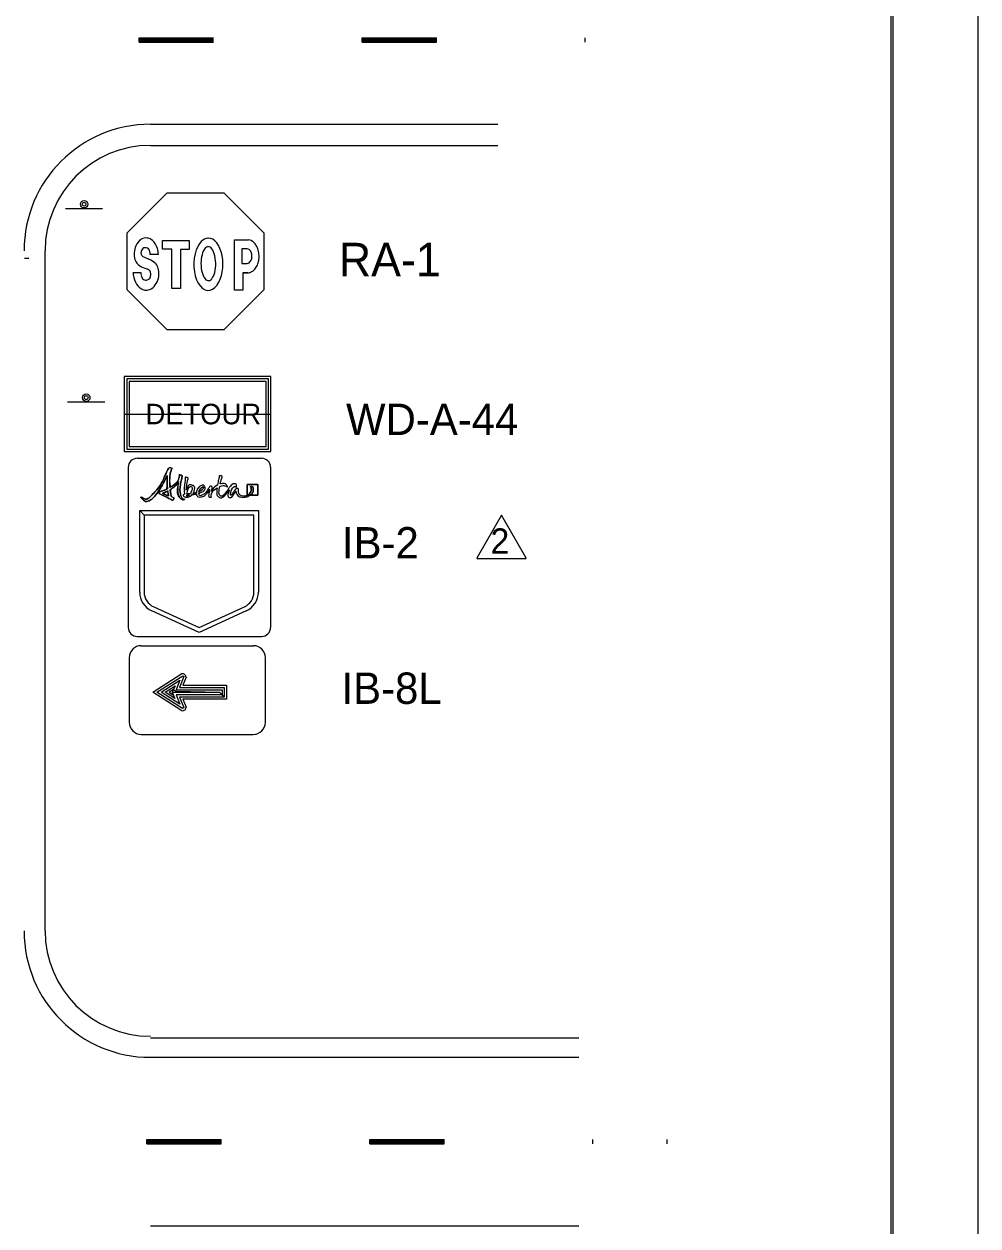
# Model space of a CAD drawing. Extents: x 1482 to 1692, y 225 to 494.
# Drawn here: x 1637.6 to 1692.4, y 314.2 to 383.2 of the extents above; entities that cross this region are included whole.
import ezdxf

# ---------------------------------------------------------------- set-up
doc = ezdxf.new("R2010")
doc.units = 0
for name, color, linetype in [('Level 17', 7, 'Continuous'), ('Level 2', 7, 'Continuous'), ('Level 53', 7, 'Continuous'), ('Level 60', 7, 'Continuous')]:
    doc.layers.add(name, color=color, linetype=linetype)

msp = doc.modelspace()

# ---------------------------------------------------------------- linework, layer by layer
at = {"layer": 'Level 17'}
for p, q in [((1640.01, 372.609), (1642.143, 372.609)), ((1645.583, 370.269), (1645.583, 370.772)), ((1645.583, 370.772), (1647.113, 370.772)), ((1647.113, 370.772), (1647.113, 370.257)), ((1648.171, 370.41), (1648.191, 370.414)), ((1648.191, 370.899), (1648.205, 370.9)), ((1649.717, 367.924), (1649.717, 370.798)), ((1649.717, 370.798), (1650.521, 370.798)), ((1637.65, 369.75), (1637.906, 369.75)), ((1645.349, 369.969), (1644.857, 369.969)), ((1646.111, 370.269), (1645.583, 370.269)), ((1646.111, 368.008), (1646.111, 370.269)), ((1647.113, 370.257), (1646.609, 370.257)), ((1646.609, 370.257), (1646.609, 368.008)), ((1650.137, 370.282), (1650.137, 369.447)), ((1650.449, 370.282), (1650.137, 370.282)), ((1650.449, 370.282), (1650.137, 370.282)), ((1650.137, 370.282), (1650.137, 369.447)), ((1650.137, 369.447), (1650.443, 369.447)), ((1650.137, 369.447), (1650.443, 369.447)), ((1643.893, 368.937), (1644.343, 368.937)), ((1644.035, 368.368), (1644.033, 368.37)), ((1650.481, 368.912), (1650.195, 368.904)), ((1650.195, 368.904), (1650.495, 368.904)), ((1650.195, 368.904), (1650.195, 367.924)), ((1646.609, 368.008), (1646.111, 368.008)), ((1650.195, 367.924), (1649.717, 367.924)), ((1640.136, 361.512), (1642.269, 361.512)), ((1643.382, 360.81), (1651.819, 360.81)), ((1644.367, 347.509), (1650.804, 347.509)), ((1643.683, 343.125), (1643.683, 346.823)), ((1651.482, 346.823), (1651.482, 343.125)), ((1645.021, 344.843), (1646.634, 345.873)), ((1646.935, 345.707), (1646.743, 345.247)), ((1646.743, 345.247), (1649.258, 345.247)), ((1649.258, 345.247), (1649.258, 344.447)), ((1646.634, 343.819), (1645.021, 344.843)), ((1646.743, 344.447), (1646.941, 343.985)), ((1649.258, 344.447), (1646.749, 344.447)), ((1644.17, 342.776), (1644.17, 342.776)), ((1644.361, 342.428), (1650.798, 342.428))]:
    msp.add_line(p, q, dxfattribs=at)
for points in [[(1651.407, 367.944), (1649.113, 365.65), (1645.846, 365.65), (1643.553, 367.944), (1643.553, 371.211), (1645.846, 373.503), (1649.113, 373.503), (1651.407, 371.211)], [(1651.813, 362.964), (1643.388, 362.964), (1643.388, 358.656), (1651.813, 358.656)], [(1651.672, 362.822), (1643.527, 362.822), (1643.527, 358.796), (1651.672, 358.796)], [(1651.532, 362.683), (1643.668, 362.683), (1643.668, 358.938), (1651.532, 358.938)]]:
    msp.add_lwpolyline(points, close=True, dxfattribs=at)
for points in [[(1649.124, 344.569), (1646.551, 344.569), (1646.806, 343.973), (1646.737, 343.909), (1645.258, 344.843), (1646.743, 345.791), (1646.814, 345.752), (1646.551, 345.119), (1649.13, 345.119), (1649.124, 344.569), (1649.002, 344.702), (1646.359, 344.702), (1646.582, 344.151), (1645.501, 344.843), (1646.582, 345.535), (1646.359, 344.984), (1649.002, 344.984), (1649.002, 344.702), (1648.867, 344.831), (1646.148, 344.831), (1646.294, 344.485), (1645.738, 344.843), (1646.308, 345.207), (1646.224, 345.003), (1645.969, 344.843), (1646.212, 344.683), (1646.161, 344.849), (1646.224, 345.003), (1646.353, 344.913), (1648.861, 344.849), (1648.867, 344.831)], [(1649.124, 344.569), (1646.551, 344.569)]]:
    msp.add_lwpolyline(points, dxfattribs=at)
for centre, radius in [((1641.081, 372.847), 0.213), ((1641.081, 372.847), 0.107), ((1641.207, 361.751), 0.213), ((1641.207, 361.751), 0.107)]:
    msp.add_circle(centre, radius, dxfattribs=at)
for centre, radius, start, end in [((1645.178, 370.002), 1.219, 157.73321, 177.13918), ((1644.843, 370.107), 0.87, 123.3662, 155.67344), ((1644.643, 370.381), 0.532, 46.13686, 121.39871), ((1644.421, 370.089), 0.898, 14.56402, 49.00631), ((1650.479, 370.326), 0.477, 44.85284, 85.0441), ((1650.33, 370.116), 0.732, 29.22414, 48.53082), ((1650.33, 370.116), 0.732, 29.22414, 48.53082), ((1650.32, 370.045), 0.778, 13.06738, 33.76202), ((1645.027, 369.968), 1.071, 174.81715, 195.91834), ((1644.587, 370.061), 0.242, 164.13099, 238.14757), ((1644.619, 370.099), 0.264, 113.8064, 172.24074), ((1645.35, 371.28), 1.68, 237.98164, 250.97904), ((1644.598, 370.078), 0.277, 47.30173, 109.01194), ((1644.468, 370.029), 0.405, 350.44122, 39.32441), ((1644.364, 368.602), 1.175, 46.24648, 67.92633), ((1644.103, 369.947), 1.243, 0.69518, 17.14515), ((1650.402, 370.011), 0.283, 35.11978, 79.31166), ((1650.402, 370.011), 0.283, 35.11978, 79.31166), ((1650.269, 369.926), 0.44, 8.60306, 34.21696), ((1650.269, 369.926), 0.44, 8.60306, 34.21696), ((1650.297, 369.813), 0.418, 326.50855, 357.0313), ((1650.297, 369.813), 0.418, 326.50855, 357.0313), ((1650.253, 369.869), 0.468, 350.34165, 15.23421), ((1650.253, 369.869), 0.468, 350.34165, 15.23421), ((1649.622, 369.815), 1.512, 3.39027, 15.65974), ((1649.917, 369.845), 1.215, 349.75207, 2.79164), ((1649.917, 369.845), 1.215, 349.75207, 2.79164), ((1644.712, 369.937), 0.762, 200.4481, 235.11069), ((1646.664, 374.289), 5.521, 244.46241, 248.83121), ((1644.58, 368.804), 0.348, 34.20826, 74.15525), ((1644.591, 368.841), 0.319, 352.57609, 30.47756), ((1646.766, 370.751), 2.053, 219.47897, 223.42605), ((1644.152, 368.865), 1.223, 5.90969, 21.9865), ((1650.377, 369.765), 0.325, 281.91914, 325.7868), ((1650.377, 369.765), 0.325, 281.91914, 325.7868), ((1650.511, 369.414), 0.478, 295.38384, 322.61875), ((1650.31, 369.636), 0.774, 318.29225, 338.60313), ((1650.31, 369.636), 0.774, 318.29225, 338.60313), ((1649.556, 369.94), 1.588, 338.31533, 348.66985), ((1645.395, 369.004), 1.502, 182.38409, 204.95188), ((1644.977, 368.878), 1.07, 208.41538, 233.65531), ((1645.023, 368.929), 0.685, 179.01715, 193.51721), ((1644.7, 368.8), 0.344, 186.87276, 222.74491), ((1644.654, 368.831), 0.335, 230.6966, 271.45727), ((1644.629, 368.805), 0.31, 275.4374, 314.06255), ((1644.495, 368.803), 0.413, 326.25303, 358.73226), ((1644.047, 368.989), 1.361, 325.50918, 343.2894), ((1643.641, 368.869), 1.731, 351.24702, 3.9864), ((1650.511, 369.074), 0.166, 259.79086, 293.54187), ((1650.369, 369.597), 0.706, 286.60198, 299.80906), ((1644.643, 368.401), 0.489, 232.05359, 292.73967), ((1644.529, 368.666), 0.782, 293.14132, 324.99056), ((1644.368, 346.825), 0.692, 90, 180), ((1650.798, 346.825), 0.692, 0, 90), ((1646.737, 345.707), 0.199, 0.10506, 122.49855), ((1646.74, 343.984), 0.199, 237.50378, 0.10575), ((1644.368, 343.121), 0.692, 180, 270), ((1650.798, 343.121), 0.692, 270, 360)]:
    msp.add_arc(centre, radius, start, end, dxfattribs=at)
for centre, major_axis, ratio, start_param, end_param in [((1648.217, 369.403), (-0.01, -1.497), 0.558644, 3.185857, 4.129398), ((1648.217, 369.438), (0.005, -0.977), 0.432619, 3.239639, 3.888884), ((1648.217, 369.438), (0.005, -0.977), 0.432619, 0.881967, 3.190734), ((1648.217, 369.403), (-0.01, -1.497), 0.558644, 0.656861, 3.168126), ((1648.217, 369.403), (-0.01, -1.497), 0.558644, 4.129576, 6.939747), ((1648.217, 369.438), (0.005, -0.977), 0.432619, 3.890436, 7.165085)]:
    msp.add_ellipse(centre, major_axis=major_axis, ratio=ratio, start_param=start_param, end_param=end_param, dxfattribs=at)
at = {"layer": 'Level 2'}
for p, q in [((1644.246, 382.403), (1648.513, 382.403)), ((1644.246, 382.147), (1644.246, 382.403)), ((1644.246, 382.339), (1648.513, 382.339)), ((1644.246, 382.275), (1648.513, 382.275)), ((1644.246, 382.211), (1648.513, 382.211)), ((1644.246, 382.147), (1648.513, 382.147)), ((1657.046, 382.403), (1661.312, 382.403)), ((1657.046, 382.147), (1657.046, 382.403)), ((1657.046, 382.339), (1661.312, 382.339)), ((1657.046, 382.275), (1661.312, 382.275)), ((1657.046, 382.211), (1661.312, 382.211)), ((1657.046, 382.147), (1661.312, 382.147)), ((1661.312, 382.147), (1661.312, 382.403)), ((1669.845, 382.147), (1669.845, 382.403)), ((1644.89, 377.436), (1664.833, 377.436)), ((1644.89, 376.227), (1664.833, 376.227)), ((1638.842, 331.153), (1638.842, 370.179)), ((1644.132, 358.269), (1651.275, 358.269)), ((1644.132, 358.269), (1651.275, 358.269)), ((1643.614, 357.751), (1643.614, 348.564)), ((1651.793, 357.751), (1651.793, 348.564)), ((1644.275, 350.597), (1644.275, 355.265)), ((1644.275, 355.265), (1644.53, 355.009)), ((1644.53, 355.009), (1644.275, 355.265)), ((1644.275, 355.265), (1651.09, 355.265)), ((1651.09, 355.265), (1651.09, 350.597)), ((1644.53, 355.009), (1644.53, 350.597)), ((1650.834, 355.009), (1644.53, 355.009)), ((1650.834, 350.597), (1650.834, 355.009)), ((1645.079, 349.744), (1647.682, 348.56)), ((1647.682, 348.56), (1650.285, 349.744)), ((1647.682, 348.279), (1644.974, 349.511)), ((1650.391, 349.511), (1647.682, 348.279)), ((1644.132, 348.046), (1651.275, 348.046)), ((1644.89, 325.004), (1669.482, 325.004)), ((1644.89, 323.895), (1669.482, 323.895)), ((1644.689, 319.189), (1648.956, 319.189)), ((1644.689, 318.933), (1644.689, 319.189)), ((1644.689, 319.125), (1648.956, 319.125)), ((1644.689, 319.061), (1648.956, 319.061)), ((1644.689, 318.997), (1648.956, 318.997)), ((1644.689, 318.933), (1648.956, 318.933)), ((1648.956, 318.933), (1648.956, 319.189)), ((1657.489, 319.189), (1661.755, 319.189)), ((1657.489, 318.933), (1657.489, 319.189)), ((1657.489, 319.125), (1661.755, 319.125)), ((1657.489, 319.061), (1661.755, 319.061)), ((1657.489, 318.997), (1661.755, 318.997)), ((1657.489, 318.933), (1661.755, 318.933)), ((1661.755, 318.933), (1661.755, 319.189)), ((1670.288, 318.933), (1670.288, 319.189)), ((1674.555, 318.933), (1674.555, 319.189)), ((1644.89, 314.218), (1669.482, 314.218))]:
    msp.add_line(p, q, dxfattribs=at)
for centre, radius, start, end in [((1644.89, 370.179), 7.258, 90, 179.99999), ((1644.89, 370.179), 6.048, 90, 179.99999), ((1644.89, 370.179), 6.048, 90, 179.99999), ((1644.132, 357.751), 0.518, 90, 180), ((1651.275, 357.751), 0.518, 0, 90), ((1645.467, 350.597), 1.193, 180, 245.54318), ((1645.467, 350.597), 0.937, 180, 245.54318), ((1649.897, 350.597), 0.937, 294.45682, 0), ((1649.897, 350.597), 1.193, 294.45682, 0), ((1644.132, 348.564), 0.518, 180, 270), ((1651.275, 348.564), 0.518, 270, 0), ((1644.89, 331.153), 7.258, 180, 269.99999), ((1644.89, 331.153), 6.048, 180, 269.99999)]:
    msp.add_arc(centre, radius, start, end, dxfattribs=at)
at = {"layer": 'Level 53'}
msp.add_line((1650.612, 356.154), (1650.462, 356.154), dxfattribs=at)
msp.add_lwpolyline([(1650.612, 356.154), (1651.053, 356.154), (1651.053, 356.762), (1650.445, 356.762), (1650.445, 356.154), (1650.462, 356.154)], dxfattribs=at)
for points, degree in [([(1646.8, 355.933), (1646.734, 355.943), (1646.649, 356.032), (1646.623, 356.178), (1646.576, 356.442), (1646.604, 356.702), (1646.681, 357.089), (1646.696, 357.162), (1646.746, 357.289), (1646.587, 357.314), (1646.536, 357.322), (1646.562, 357.297), (1646.548, 357.23), (1646.487, 356.941), (1646.251, 356.733), (1646.014, 356.594), (1645.989, 356.924), (1646, 357.291), (1646.062, 357.516), (1646.114, 357.706), (1646.177, 357.671), (1646.099, 357.711), (1646.018, 357.753), (1645.93, 357.697), (1645.859, 357.556), (1645.789, 357.415), (1645.462, 356.647), (1644.941, 356.129), (1644.675, 355.864), (1644.433, 356), (1644.385, 356.041), (1644.346, 356.074), (1644.331, 356.023), (1644.38, 355.971), (1644.596, 355.738), (1644.911, 355.871), (1645.026, 355.986), (1645.342, 356.303), (1645.711, 356.985), (1645.86, 357.275), (1645.846, 357.112), (1645.842, 356.838), (1645.872, 356.518), (1645.711, 356.439), (1645.566, 356.393), (1645.498, 356.375), (1645.424, 356.356), (1645.378, 356.326), (1645.377, 356.291), (1645.376, 356.254), (1645.425, 356.222), (1645.497, 356.188), (1645.625, 356.128), (1645.999, 355.951), (1646.091, 355.897), (1646.17, 355.852), (1646.208, 355.887), (1646.232, 355.937), (1646.262, 356.001), (1646.178, 356.038), (1646.097, 356.063), (1646.066, 356.171), (1646.041, 356.317), (1646.024, 356.478), (1646.215, 356.595), (1646.402, 356.751), (1646.51, 356.945), (1646.483, 356.783), (1646.413, 356.229), (1646.588, 355.995), (1646.626, 355.944), (1646.711, 355.887), (1646.794, 355.896), (1646.833, 355.899), (1646.853, 355.925), (1646.849, 355.933), (1646.845, 355.941), (1646.823, 355.93), (1646.8, 355.933)], 3), ([(1646.014, 356.594), (1645.989, 356.924), (1646, 357.291), (1646.062, 357.516), (1646.114, 357.706), (1646.177, 357.671), (1646.099, 357.711), (1646.018, 357.753), (1645.93, 357.697), (1645.859, 357.556), (1645.789, 357.415), (1645.462, 356.647), (1644.941, 356.129), (1644.675, 355.864), (1644.433, 356), (1644.385, 356.041), (1644.346, 356.074), (1644.331, 356.023), (1644.38, 355.971), (1644.596, 355.738), (1644.911, 355.871), (1645.026, 355.986), (1645.342, 356.303), (1645.711, 356.985), (1645.86, 357.275)], 3), ([(1645.86, 357.275), (1645.846, 357.112), (1645.842, 356.838), (1645.872, 356.518)], 2), ([(1646.8, 355.933), (1646.734, 355.943), (1646.649, 356.032), (1646.623, 356.178), (1646.576, 356.442), (1646.604, 356.702), (1646.681, 357.089), (1646.696, 357.162), (1646.746, 357.289), (1646.587, 357.314), (1646.536, 357.322), (1646.562, 357.297), (1646.548, 357.23), (1646.487, 356.941), (1646.251, 356.733), (1646.014, 356.594)], 3), ([(1648.896, 356.801), (1648.914, 356.882), (1648.935, 356.964), (1648.957, 357.044), (1648.978, 357.118), (1649.038, 357.245), (1648.881, 357.269), (1648.831, 357.277), (1648.852, 357.253), (1648.835, 357.185), (1648.805, 357.06), (1648.767, 356.899), (1648.739, 356.736)], 3), ([(1646.024, 356.478), (1646.215, 356.595), (1646.402, 356.751), (1646.51, 356.945)], 2), ([(1646.51, 356.945), (1646.483, 356.783), (1646.413, 356.229), (1646.588, 355.995), (1646.626, 355.944), (1646.711, 355.887), (1646.794, 355.896), (1646.833, 355.899), (1646.853, 355.925), (1646.849, 355.933), (1646.845, 355.941), (1646.823, 355.93), (1646.8, 355.933)], 3), ([(1646.946, 356.435), (1646.959, 356.59), (1646.983, 356.779), (1647.018, 356.954), (1647.033, 357.028), (1647.083, 357.155), (1646.924, 357.179), (1646.874, 357.187), (1646.881, 357.163), (1646.886, 357.095), (1646.891, 357.003), (1646.789, 356.447), (1646.843, 356.203)], 3), ([(1647.338, 356.255), (1647.451, 356.438), (1647.441, 356.686), (1647.276, 356.728), (1647.084, 356.777), (1646.987, 356.59), (1646.946, 356.435)], 3), ([(1646.987, 356.22), (1647.013, 356.415), (1647.114, 356.686), (1647.241, 356.643), (1647.314, 356.617), (1647.275, 356.389), (1647.182, 356.237)], 3), ([(1647.672, 356.261), (1647.698, 356.269), (1647.722, 356.278), (1647.742, 356.286), (1647.982, 356.393), (1648.065, 356.554), (1648.004, 356.652), (1647.946, 356.745), (1647.78, 356.717), (1647.649, 356.579), (1647.584, 356.511), (1647.535, 356.394), (1647.529, 356.287)], 3), ([(1648.401, 356.374), (1648.417, 356.45), (1648.44, 356.533), (1648.442, 356.589), (1648.444, 356.648), (1648.403, 356.662), (1648.387, 356.666), (1648.353, 356.676), (1648.311, 356.659), (1648.27, 356.601), (1648.174, 356.465), (1648.052, 356.251), (1647.867, 356.161), (1647.734, 356.096), (1647.676, 356.161), (1647.672, 356.261)], 3), ([(1647.801, 356.566), (1647.882, 356.641), (1647.922, 356.636), (1647.932, 356.616), (1647.955, 356.572), (1647.86, 356.419), (1647.678, 356.335)], 3), ([(1648.739, 356.736), (1648.61, 356.662), (1648.489, 356.538), (1648.401, 356.374)], 2), ([(1650.274, 356.1), (1650.025, 356.1), (1649.96, 356.294), (1649.948, 356.39), (1649.94, 356.454), (1649.954, 356.546), (1649.844, 356.534), (1649.767, 356.525), (1649.697, 356.375), (1649.599, 356.248), (1649.515, 356.14), (1649.478, 356.15), (1649.497, 356.243), (1649.521, 356.36), (1649.619, 356.634), (1649.73, 356.654), (1649.782, 356.663), (1649.8, 356.573), (1649.824, 356.629), (1649.848, 356.686), (1649.826, 356.809), (1649.711, 356.809), (1649.63, 356.809), (1649.533, 356.723), (1649.453, 356.626), (1649.384, 356.541), (1649.034, 356.025), (1648.887, 356.136), (1648.818, 356.188), (1648.824, 356.4), (1648.867, 356.65)], 3), ([(1648.867, 356.65), (1649.041, 356.717), (1649.186, 356.695), (1649.268, 356.656), (1649.309, 356.636), (1649.314, 356.639), (1649.297, 356.684), (1649.272, 356.749), (1649.131, 356.851), (1648.912, 356.805), (1648.907, 356.803), (1648.902, 356.802), (1648.896, 356.801)], 3), ([(1650.445, 356.762), (1650.445, 356.762), (1650.445, 356.154), (1650.445, 356.154), (1650.445, 356.154), (1650.462, 356.154), (1650.462, 356.154), (1650.594, 356.233), (1650.683, 356.384), (1650.683, 356.508), (1650.683, 356.616), (1650.626, 356.61), (1650.632, 356.625), (1650.651, 356.668), (1650.785, 356.644), (1650.793, 356.492), (1650.799, 356.363), (1650.732, 356.239), (1650.612, 356.154), (1650.612, 356.154), (1651.053, 356.154), (1651.053, 356.154), (1651.053, 356.154), (1651.053, 356.762), (1651.053, 356.762), (1651.053, 356.762), (1650.445, 356.762), (1650.445, 356.762)], 3), ([(1650.462, 356.154), (1650.594, 356.233), (1650.683, 356.384), (1650.683, 356.508), (1650.683, 356.616), (1650.626, 356.61), (1650.632, 356.625), (1650.651, 356.668), (1650.785, 356.644), (1650.793, 356.492), (1650.799, 356.363), (1650.732, 356.239), (1650.612, 356.154)], 3), ([(1645.872, 356.518), (1645.711, 356.439), (1645.566, 356.393), (1645.498, 356.375), (1645.424, 356.356), (1645.378, 356.326), (1645.377, 356.291), (1645.376, 356.254), (1645.425, 356.222), (1645.497, 356.188), (1645.625, 356.128), (1645.999, 355.951), (1646.091, 355.897), (1646.17, 355.852), (1646.208, 355.887), (1646.232, 355.937), (1646.262, 356.001), (1646.178, 356.038), (1646.097, 356.063)], 3), ([(1645.581, 356.264), (1645.665, 356.294), (1645.772, 356.339), (1645.885, 356.399)], 2), ([(1645.581, 356.264), (1645.665, 356.294), (1645.772, 356.339), (1645.885, 356.399), (1645.9, 356.27), (1645.917, 356.176), (1645.935, 356.107), (1645.852, 356.137), (1645.734, 356.185), (1645.581, 356.264)], 3), ([(1645.935, 356.107), (1645.852, 356.137), (1645.734, 356.185), (1645.581, 356.264)], 2), ([(1645.885, 356.399), (1645.9, 356.27), (1645.917, 356.176), (1645.935, 356.107)], 2), ([(1646.097, 356.063), (1646.066, 356.171), (1646.041, 356.317), (1646.024, 356.478)], 2), ([(1646.843, 356.203), (1646.774, 356.181), (1646.746, 356.129), (1646.834, 356.075), (1646.895, 356.038), (1647.029, 356.025), (1647.164, 356.092), (1647.212, 356.115), (1647.254, 356.149), (1647.289, 356.188)], 3), ([(1646.967, 356.102), (1646.975, 356.109), (1646.981, 356.12), (1646.981, 356.133), (1646.981, 356.142), (1646.981, 356.15), (1646.981, 356.159)], 3), ([(1647.021, 356.102), (1646.999, 356.099), (1646.981, 356.099), (1646.967, 356.102)], 2), ([(1646.981, 356.159), (1647.016, 356.161), (1647.069, 356.165), (1647.133, 356.171)], 2), ([(1647.182, 356.237), (1647.121, 356.231), (1647.056, 356.225), (1646.987, 356.22)], 2), ([(1647.133, 356.171), (1647.1, 356.134), (1647.062, 356.109), (1647.021, 356.102)], 2), ([(1647.289, 356.188), (1647.369, 356.199), (1647.454, 356.212), (1647.531, 356.227)], 2), ([(1647.529, 356.287), (1647.473, 356.275), (1647.409, 356.265), (1647.338, 356.255)], 2), ([(1647.531, 356.227), (1647.544, 356.12), (1647.614, 356.038), (1647.776, 356.053), (1648.007, 356.074), (1648.212, 356.358), (1648.289, 356.494)], 3), ([(1647.678, 356.335), (1647.694, 356.417), (1647.737, 356.507), (1647.801, 356.566)], 2), ([(1648.289, 356.494), (1648.275, 356.348), (1648.18, 356.028), (1648.342, 356.045), (1648.406, 356.051), (1648.378, 356.061), (1648.382, 356.116), (1648.396, 356.309), (1648.556, 356.472), (1648.715, 356.572)], 3), ([(1648.715, 356.572), (1648.688, 356.336), (1648.697, 356.126), (1648.804, 356.059), (1649.001, 355.936), (1649.28, 356.26), (1649.433, 356.458)], 3), ([(1649.433, 356.458), (1649.355, 356.282), (1649.311, 356.057), (1649.428, 356.022), (1649.566, 355.982), (1649.674, 356.21), (1649.801, 356.385)], 3), ([(1649.801, 356.385), (1649.816, 356.26), (1649.9, 356.044), (1650.237, 356.044), (1650.388, 356.044), (1650.517, 356.086), (1650.612, 356.154)], 3), ([(1650.462, 356.154), (1650.406, 356.12), (1650.342, 356.1), (1650.274, 356.1)], 2)]:
    msp.add_open_spline(points, degree=degree, dxfattribs=at)
at = {"layer": 'Level 60'}
for points in [[(1482.41, 493.623), (1692.41, 493.623), (1692.41, 224.631), (1482.41, 224.631)], [(1493.127, 487.958), (1687.519, 487.958), (1687.519, 230.208), (1493.127, 230.208)], [(1500.536, 487.818), (1687.41, 487.818), (1687.41, 230.436), (1500.536, 230.436)]]:
    msp.add_lwpolyline(points, close=True, dxfattribs=at)
for points in [[(1665.048, 354.999), (1663.655, 352.574)], [(1666.442, 352.574), (1665.048, 354.999)], [(1663.655, 352.574), (1663.629, 352.529), (1666.468, 352.529), (1666.442, 352.574)]]:
    msp.add_lwpolyline(points, dxfattribs=at)

# ---------------------------------------------------------------- texts
at = {"layer": 'Level 17'}
for s, height, p in [('RA-1', 1.92, (1655.71, 368.715)), ('WD-A-44', 1.8, (1656.122, 359.607)), ('IB-2', 1.8, (1655.886, 352.52)), ('IB-8L', 1.8, (1655.861, 344.177))]:
    msp.add_text(s, height=height, rotation=359.99999, dxfattribs=at).set_placement(p)
msp.add_text('DETOUR', height=1.1758, dxfattribs=at).set_placement((1644.608, 360.222))
at = {"layer": 'Level 60'}
msp.add_text('2', height=1.448, rotation=360, dxfattribs=at).set_placement((1664.421, 352.798))

doc.saveas('drawing.dxf')
